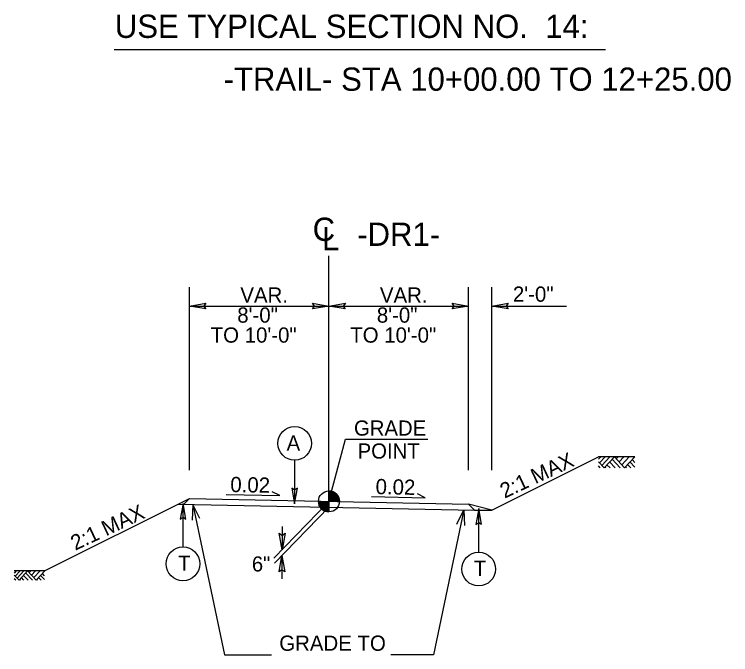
# Model space of a CAD drawing. Extents: x 1901670 to 1902225, y 193498 to 194278.
# Drawn here: x 1902071.22 to 1902102.02, y 193548.55 to 193576.09 of the extents above; entities that cross this region are included whole.
import ezdxf

# ---------------------------------------------------------------- set-up
doc = ezdxf.new("R2010")
doc.units = 0
for name, color, linetype in [('Old_Level_1', 7, 'Continuous'), ('Old_Level_11', 7, 'Continuous'), ('Old_Level_2', 7, 'Continuous'), ('Old_Level_20', 7, 'Continuous'), ('Prop Dimension', 7, 'Continuous'), ('Prop Lane Arrow CELL', 7, 'Continuous'), ('Typical Hinge Slope Arterial CELL', 7, 'Continuous'), ('Typical Hinge Slope Interstate CELL', 7, 'Continuous'), ('Typical Terminator CELL', 7, 'Continuous'), ('Typical Text Grade Point CELL', 7, 'Continuous')]:
    doc.layers.add(name, color=color, linetype=linetype)

# ---------------------------------------------------------------- blocks, each defined once
blk = doc.blocks.new('TERMINATOR')
at = {"layer": 'Typical Terminator CELL'}
blk.add_lwpolyline([(-0.469, 0.081), (0, 0), (-0.471, -0.083), (-0.411, 0)], close=True, dxfattribs=at)

msp = doc.modelspace()

# ---------------------------------------------------------------- linework, layer by layer
at = {"layer": 'Old_Level_1'}
for p, q in [((1902084.745, 193555.143), (1902084.745, 193565.702)), ((1902080.322, 193555.438), (1902082.637, 193555.39)), ((1902082.637, 193555.39), (1902082.304, 193555.557)), ((1902084.745, 193555.143), (1902084.745, 193555.593)), ((1902088.883, 193555.3), (1902088.55, 193555.467)), ((1902084.745, 193555.143), (1902082.38, 193552.7)), ((1902084.295, 193555.143), (1902084.745, 193555.143)), ((1902084.744, 193554.693), (1902084.745, 193555.143)), ((1902084.745, 193555.143), (1902084.744, 193554.693)), ((1902085.195, 193555.143), (1902084.745, 193555.143)), ((1902086.568, 193555.349), (1902088.883, 193555.3)), ((1902084.735, 193554.893), (1902082.402, 193552.484)), ((1902082.735, 193554.067), (1902082.735, 193553.067)), ((1902082.723, 193552.815), (1902082.723, 193551.815)), ((1902071.303, 193552.15), (1902071.218, 193552.059)), ((1902071.463, 193552.15), (1902071.256, 193551.928)), ((1902071.63, 193552.15), (1902071.34, 193551.839)), ((1902071.791, 193552.15), (1902071.42, 193551.752)), ((1902072.001, 193551.748), (1902071.708, 193552.062)), ((1902072.156, 193551.757), (1902071.791, 193552.15)), ((1902071.923, 193552.15), (1902071.856, 193552.079)), ((1902072.124, 193552.15), (1902071.957, 193551.971)), ((1902072.323, 193552.15), (1902072.056, 193551.864)), ((1902072.518, 193552.146), (1902072.156, 193551.757)), ((1902072.518, 193551.945), (1902072.425, 193552.046)), ((1902071.42, 193551.752), (1902071.218, 193551.969)), ((1902071.285, 193551.748), (1902071.218, 193551.819)), ((1902071.486, 193551.748), (1902071.451, 193551.785)), ((1902071.633, 193551.748), (1902071.525, 193551.864)), ((1902071.816, 193551.748), (1902071.616, 193551.962)), ((1902072.219, 193551.748), (1902072.183, 193551.786)), ((1902072.374, 193551.748), (1902072.261, 193551.869)), ((1902072.518, 193551.779), (1902072.347, 193551.962))]:
    msp.add_line(p, q, dxfattribs=at)
for points in [[(1902084.749, 193555.593), (1902084.749, 193555.593), (1902084.749, 193555.143)], [(1902084.758, 193555.593), (1902084.758, 193555.143)], [(1902084.767, 193555.592), (1902084.767, 193555.143)], [(1902084.776, 193555.592), (1902084.776, 193555.143)], [(1902084.785, 193555.591), (1902084.785, 193555.143)], [(1902084.794, 193555.59), (1902084.794, 193555.143)], [(1902084.803, 193555.589), (1902084.803, 193555.143)], [(1902084.812, 193555.588), (1902084.812, 193555.143)], [(1902084.821, 193555.587), (1902084.821, 193555.143)], [(1902084.83, 193555.585), (1902084.83, 193555.143)], [(1902084.839, 193555.583), (1902084.839, 193555.143)], [(1902084.848, 193555.581), (1902084.848, 193555.143)], [(1902084.857, 193555.579), (1902084.857, 193555.143)], [(1902084.866, 193555.576), (1902084.866, 193555.143)], [(1902084.875, 193555.574), (1902084.875, 193555.143)], [(1902084.884, 193555.571), (1902084.884, 193555.143)], [(1902084.893, 193555.568), (1902084.893, 193555.143)], [(1902084.902, 193555.565), (1902084.902, 193555.143)], [(1902084.911, 193555.561), (1902084.911, 193555.143)], [(1902084.92, 193555.557), (1902084.92, 193555.143)], [(1902084.929, 193555.553), (1902084.929, 193555.143)], [(1902084.938, 193555.549), (1902084.938, 193555.143)], [(1902084.947, 193555.545), (1902084.947, 193555.143)], [(1902084.956, 193555.54), (1902084.956, 193555.143)], [(1902084.965, 193555.535), (1902084.965, 193555.143)], [(1902084.974, 193555.53), (1902084.974, 193555.143)], [(1902084.983, 193555.525), (1902084.983, 193555.143)], [(1902084.992, 193555.519), (1902084.992, 193555.143)], [(1902085.001, 193555.513), (1902085.001, 193555.143)], [(1902085.01, 193555.506), (1902085.01, 193555.143)], [(1902085.019, 193555.5), (1902085.019, 193555.143)], [(1902085.028, 193555.493), (1902085.028, 193555.143)], [(1902085.037, 193555.485), (1902085.037, 193555.143)], [(1902085.046, 193555.477), (1902085.046, 193555.143)], [(1902085.055, 193555.469), (1902085.055, 193555.143)], [(1902085.064, 193555.46), (1902085.064, 193555.143)], [(1902085.073, 193555.451), (1902085.073, 193555.143)], [(1902085.082, 193555.441), (1902085.082, 193555.143)], [(1902085.091, 193555.43), (1902085.091, 193555.143)], [(1902085.1, 193555.419), (1902085.1, 193555.143)], [(1902085.109, 193555.407), (1902085.109, 193555.143)], [(1902085.118, 193555.394), (1902085.118, 193555.143)], [(1902085.127, 193555.38), (1902085.127, 193555.143)], [(1902085.136, 193555.365), (1902085.136, 193555.143)], [(1902084.297, 193555.143), (1902084.297, 193555.094)], [(1902084.306, 193555.143), (1902084.306, 193555.041)], [(1902084.315, 193555.143), (1902084.315, 193555.009)], [(1902084.324, 193555.143), (1902084.324, 193554.982)], [(1902084.333, 193555.143), (1902084.333, 193554.961)], [(1902084.342, 193555.143), (1902084.342, 193554.942)], [(1902084.351, 193555.143), (1902084.351, 193554.925)], [(1902084.36, 193555.143), (1902084.36, 193554.909)], [(1902084.369, 193555.143), (1902084.369, 193554.895)], [(1902084.378, 193555.143), (1902084.378, 193554.882)], [(1902084.387, 193555.143), (1902084.387, 193554.87)], [(1902084.396, 193555.143), (1902084.396, 193554.859)], [(1902084.405, 193555.143), (1902084.405, 193554.848)], [(1902084.414, 193555.143), (1902084.414, 193554.838)], [(1902084.423, 193555.143), (1902084.423, 193554.828)], [(1902084.432, 193555.143), (1902084.432, 193554.819)], [(1902084.441, 193555.143), (1902084.441, 193554.811)], [(1902084.45, 193555.143), (1902084.45, 193554.803)], [(1902084.459, 193555.143), (1902084.459, 193554.795)], [(1902084.468, 193555.143), (1902084.468, 193554.788)], [(1902084.477, 193555.143), (1902084.477, 193554.781)], [(1902084.486, 193555.143), (1902084.486, 193554.775)], [(1902084.495, 193555.143), (1902084.495, 193554.769)], [(1902084.504, 193555.143), (1902084.504, 193554.763)], [(1902084.513, 193555.143), (1902084.513, 193554.757)], [(1902084.522, 193555.143), (1902084.522, 193554.752)], [(1902084.531, 193555.143), (1902084.531, 193554.747)], [(1902084.54, 193555.143), (1902084.54, 193554.742)], [(1902084.549, 193555.143), (1902084.549, 193554.738)], [(1902084.558, 193555.143), (1902084.558, 193554.734)], [(1902084.567, 193555.143), (1902084.567, 193554.73)], [(1902084.576, 193555.143), (1902084.576, 193554.726)], [(1902084.585, 193555.143), (1902084.585, 193554.722)], [(1902084.594, 193555.143), (1902084.594, 193554.719)], [(1902084.603, 193555.143), (1902084.603, 193554.716)], [(1902084.612, 193555.143), (1902084.612, 193554.713)], [(1902084.621, 193555.143), (1902084.621, 193554.711)], [(1902084.63, 193555.143), (1902084.63, 193554.708)], [(1902084.639, 193555.143), (1902084.639, 193554.706)], [(1902084.648, 193555.143), (1902084.648, 193554.704)], [(1902084.657, 193555.143), (1902084.657, 193554.702)], [(1902084.666, 193555.143), (1902084.666, 193554.7)], [(1902084.675, 193555.143), (1902084.675, 193554.699)], [(1902084.684, 193555.143), (1902084.684, 193554.697)], [(1902084.693, 193555.143), (1902084.693, 193554.696)], [(1902084.702, 193555.143), (1902084.702, 193554.695)], [(1902084.711, 193555.143), (1902084.711, 193554.694)], [(1902084.72, 193555.143), (1902084.72, 193554.694)], [(1902084.729, 193555.143), (1902084.729, 193554.693)], [(1902084.738, 193555.143), (1902084.738, 193554.693), (1902084.738, 193554.693)], [(1902085.145, 193555.349), (1902085.145, 193555.143)], [(1902085.154, 193555.33), (1902085.154, 193555.143)], [(1902085.163, 193555.309), (1902085.163, 193555.143)], [(1902085.172, 193555.284), (1902085.172, 193555.143)], [(1902085.181, 193555.253), (1902085.181, 193555.143)], [(1902085.19, 193555.207), (1902085.19, 193555.143)], [(1902079.192, 193554.401), (1902078.898, 193555.01), (1902078.871, 193554.335)], [(1902078.898, 193555.01), (1902080.25, 193548.55), (1902082.27, 193548.55)], [(1902090.542, 193554.777), (1902089.239, 193548.55), (1902087.412, 193548.55)], [(1902090.249, 193554.168), (1902090.542, 193554.777), (1902090.57, 193554.102)], [(1902072.518, 193552.15), (1902071.218, 193552.15)]]:
    msp.add_lwpolyline(points, dxfattribs=at)
msp.add_circle((1902084.744, 193555.143), 0.45, dxfattribs=at)
for start, end in [(359.9905, 89.9905), (179.9905, 269.9905)]:
    msp.add_arc((1902084.744, 193555.143), 0.45, start, end, dxfattribs=at)
at = {"layer": 'Old_Level_11'}
for p, q in [((1902075.514, 193574.585), (1902096.641, 193574.585)), ((1902083.27, 193556.913), (1902083.27, 193555.039)), ((1902078.47, 193553.183), (1902078.47, 193555.057)), ((1902091.183, 193552.957), (1902091.183, 193554.831))]:
    msp.add_line(p, q, dxfattribs=at)
for points in [[(1902083.155, 193555.71), (1902083.27, 193555.039), (1902083.39, 193555.714), (1902083.27, 193555.628)], [(1902078.585, 193554.386), (1902078.47, 193555.057), (1902078.35, 193554.382), (1902078.47, 193554.468)], [(1902091.298, 193554.16), (1902091.183, 193554.831), (1902091.063, 193554.156), (1902091.183, 193554.242)]]:
    msp.add_lwpolyline(points, close=True, dxfattribs=at)
for centre in [(1902083.27, 193557.638), (1902078.469, 193552.458), (1902091.183, 193552.232)]:
    msp.add_circle(centre, 0.725, dxfattribs=at)
at = {"layer": 'Prop Dimension'}
for p, q in [((1902078.745, 193556.481), (1902078.745, 193564.363)), ((1902090.745, 193556.481), (1902090.745, 193564.363)), ((1902091.745, 193556.481), (1902091.745, 193564.363)), ((1902078.745, 193563.547), (1902084.745, 193563.547)), ((1902084.745, 193563.547), (1902090.745, 193563.547)), ((1902091.745, 193563.547), (1902094.952, 193563.547))]:
    msp.add_line(p, q, dxfattribs=at)
at = {"layer": 'Prop Lane Arrow CELL'}
for p, q in [((1902096.433, 193557.066), (1902096.331, 193556.957)), ((1902096.625, 193557.066), (1902096.376, 193556.8)), ((1902096.824, 193557.066), (1902096.476, 193556.693)), ((1902097.018, 193557.066), (1902096.573, 193556.588)), ((1902097.27, 193556.583), (1902096.919, 193556.96)), ((1902097.456, 193556.594), (1902097.018, 193557.066)), ((1902097.176, 193557.066), (1902097.096, 193556.981)), ((1902097.417, 193557.066), (1902097.217, 193556.851)), ((1902097.656, 193557.066), (1902097.336, 193556.722)), ((1902097.891, 193557.062), (1902097.456, 193556.594)), ((1902097.891, 193556.821), (1902097.779, 193556.941)), ((1902096.573, 193556.588), (1902096.331, 193556.849)), ((1902096.411, 193556.583), (1902096.331, 193556.669)), ((1902096.652, 193556.583), (1902096.61, 193556.628)), ((1902096.829, 193556.583), (1902096.698, 193556.723)), ((1902097.048, 193556.583), (1902096.808, 193556.841)), ((1902097.531, 193556.583), (1902097.489, 193556.629)), ((1902097.718, 193556.583), (1902097.582, 193556.729)), ((1902097.891, 193556.621), (1902097.685, 193556.841)), ((1902078.499, 193555.018), (1902078.745, 193555.263)), ((1902078.745, 193555.263), (1902090.745, 193555.023)), ((1902078.264, 193555.023), (1902091, 193554.768)), ((1902091, 193554.768), (1902090.745, 193555.023)), ((1902091, 193554.768), (1902091.745, 193554.773))]:
    msp.add_line(p, q, dxfattribs=at)
msp.add_lwpolyline([(1902097.891, 193557.066), (1902096.331, 193557.066)], dxfattribs=at)
at = {"layer": 'Typical Hinge Slope Arterial CELL'}
for p, q in [((1902091.745, 193554.773), (1902096.331, 193557.066)), ((1902072.518, 193552.15), (1902078.745, 193555.263))]:
    msp.add_line(p, q, dxfattribs=at)
at = {"layer": 'Typical Hinge Slope Interstate CELL'}
msp.add_line((1902091.745, 193554.773), (1902090.745, 193555.023), dxfattribs=at)
at = {"layer": 'Typical Text Grade Point CELL'}
for p, q in [((1902084.745, 193555.143), (1902085.457, 193557.816)), ((1902085.457, 193557.816), (1902088.995, 193557.816))]:
    msp.add_line(p, q, dxfattribs=at)

# ---------------------------------------------------------------- block references
at = {"layer": 'Old_Level_1', "xscale": 1.5, "yscale": 1.5}
for p, rotation in [((1902082.735, 193553.067), -90), ((1902082.723, 193552.815), 90)]:
    msp.add_blockref('TERMINATOR', p, dxfattribs=dict(at, rotation=rotation))
at = {"layer": 'Prop Dimension', "xscale": 1.5, "yscale": 1.5, "rotation": 180}
for p in [(1902078.745, 193563.547), (1902084.745, 193563.547), (1902091.745, 193563.547)]:
    msp.add_blockref('TERMINATOR', p, dxfattribs=at)
at = {"layer": 'Prop Dimension', "xscale": 1.5, "yscale": 1.5}
for p in [(1902084.745, 193563.547), (1902090.745, 193563.547)]:
    msp.add_blockref('TERMINATOR', p, dxfattribs=at)

# ---------------------------------------------------------------- texts
at = {"layer": 'Old_Level_1'}
for p in [(1902092.293, 193555.257), (1902073.835, 193553.018)]:
    msp.add_text('2:1 MAX', height=0.656, rotation=25.1183, dxfattribs=at).set_placement(p)
for s, height, p in [('6"', 0.6491, (1902081.431, 193552.128)), ('GRADE TO ', 0.656, (1902082.608, 193548.717))]:
    msp.add_text(s, height=height, dxfattribs=at).set_placement(p)
at = {"layer": 'Old_Level_11'}
for s, p in [('USE TYPICAL SECTION NO.  14:', (1902075.539, 193575.079)), ('-TRAIL- STA 10+00.00 TO 12+25.00', (1902080.215, 193572.805))]:
    msp.add_text(s, height=1, dxfattribs=at).set_placement(p)
at = {"layer": 'Old_Level_2'}
msp.add_text('C', height=1, dxfattribs=at).set_placement((1902084.043, 193566.348))
for s, height, rotation, p in [('-DR1-', 1, 359.9469, (1902085.959, 193566.135)), ('L', 1, 359.9469, (1902084.445, 193565.944)), ('0.02', 0.656, 358.8084, (1902080.499, 193555.546)), ('0.02', 0.656, 358.8084, (1902086.745, 193555.456))]:
    msp.add_text(s, height=height, rotation=rotation, dxfattribs=at).set_placement(p)
at = {"layer": 'Old_Level_20'}
for s, p in [('A', (1902082.926, 193557.332)), ('T', (1902078.259, 193552.165)), ('T', (1902090.972, 193551.939))]:
    msp.add_text(s, height=0.649, dxfattribs=at).set_placement(p)
at = {"layer": 'Prop Dimension'}
for s, p in [('VAR.', (1902080.936, 193563.691)), ('VAR.', (1902086.936, 193563.691)), ('2\'-0"', (1902092.654, 193563.731)), ('8\'-0"', (1902080.803, 193562.831)), ('8\'-0"', (1902086.803, 193562.831)), ('TO 10\'-0"', (1902079.66, 193561.971)), ('TO 10\'-0"', (1902085.66, 193561.971))]:
    msp.add_text(s, height=0.656, dxfattribs=at).set_placement(p)
at = {"layer": 'Typical Text Grade Point CELL'}
for s, p in [('GRADE', (1902085.821, 193557.972)), ('POINT', (1902085.978, 193556.984))]:
    msp.add_text(s, height=0.6525, dxfattribs=at).set_placement(p)

doc.saveas('drawing.dxf')
